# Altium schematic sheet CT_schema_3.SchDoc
size 349 x 342 mm
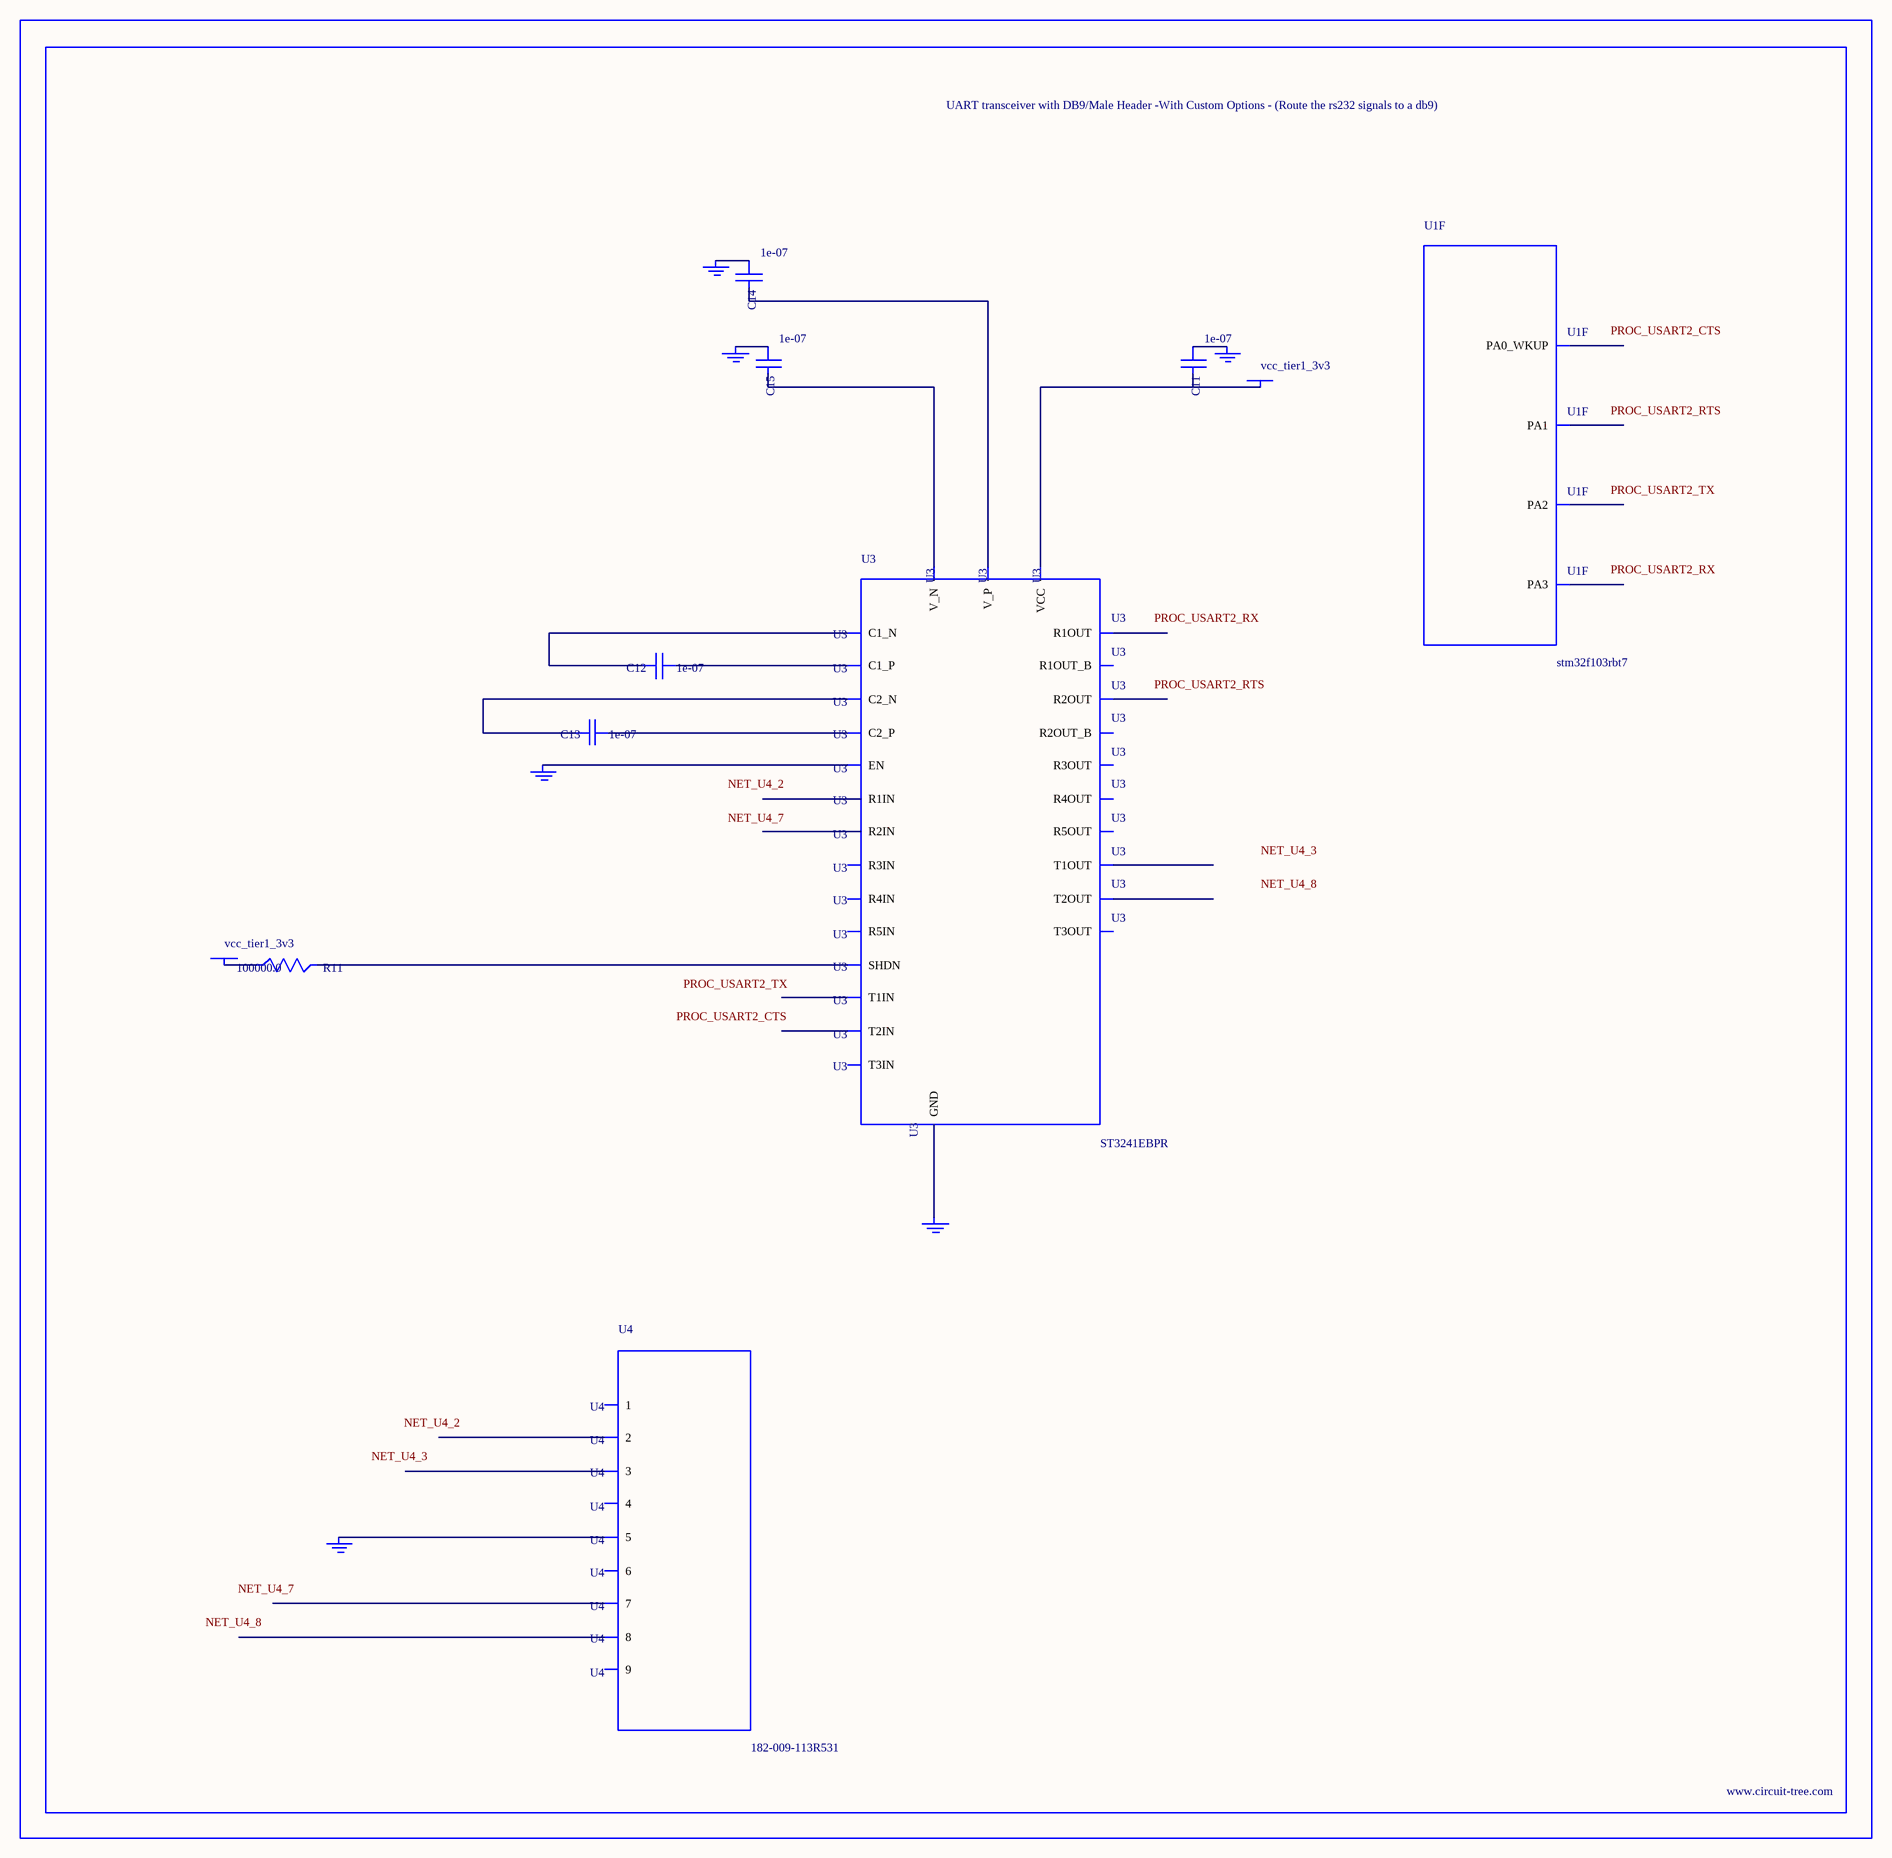
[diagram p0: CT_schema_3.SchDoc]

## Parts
BORDER2  (no value)
C11  1e-07  [C0402]
C12  1e-07  [C0402]
C13  1e-07  [C0402]
C14  1e-07  [C0402]
C15  1e-07  [C0402]
GND_INSTANCE_2_0  (no value)
GND_INSTANCE_2_1  (no value)
GND_INSTANCE_2_2  (no value)
GND_INSTANCE_2_3  (no value)
GND_INSTANCE_2_4  (no value)
GND_INSTANCE_2_5  (no value)
POWER_INSTANCE_2_0  vcc_tier1_3v3
POWER_INSTANCE_2_1  vcc_tier1_3v3
R11  100000.0  [R0603]
U1  stm32f103rbt7  [LQFP64]  (part F of 7)
U3  ST3241EBPR  [SSOP-28]
U4  182-009-113R531  [182-009-MALE]

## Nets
NetC11_1: C11.1 GND_INSTANCE_2_2.0(GND)
NetC11_2: C11.2 POWER_INSTANCE_2_1.0(PWR) U3.26(VCC)
NetC12_1: C12.1 U3.28(C1_P)
NetC12_2: C12.2 U3.24(C1_N)
NetC13_1: C13.1 U3.1(C2_P)
NetC13_2: C13.2 U3.2(C2_N)
NetC14_1: C14.1 GND_INSTANCE_2_3.0(GND)
NetC14_2: C14.2 U3.27(V_P)
NetC15_1: C15.1 GND_INSTANCE_2_0.0(GND)
NetC15_2: C15.2 U3.3(V_N)
NetGND_INSTANCE_2_1_0: GND_INSTANCE_2_1.0(GND) U3.23(EN)
NetGND_INSTANCE_2_4_0: GND_INSTANCE_2_4.0(GND) U3.25(GND)
NetGND_INSTANCE_2_5_0: GND_INSTANCE_2_5.0(GND) U4.5
NetPOWER_INSTANCE_2_0_0: POWER_INSTANCE_2_0.0(PWR) R11.1
NetR11_2: R11.2 U3.22(SHDN)

Not connected (* = marked no-connect by the designer): U1 14(PA0_WKUP) 15(PA1) 16(PA2) 17(PA3); U3 4(R1IN) 5(R2IN) 6(R3IN) 7(R4IN) 8(R5IN) 9(T1OUT) 10(T2OUT) 11(T3OUT) 12(T3IN) 13(T2IN) 14(T1IN) 15(R5OUT) 16(R4OUT) 17(R3OUT) 18(R2OUT) 19(R1OUT) 20(R2OUT_B) 21(R1OUT_B); U4 1 2 3 4 6 7 8 9

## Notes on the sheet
- Labels drawn without touching a wire or pin: NET_U4_2, NET_U4_3, NET_U4_7, NET_U4_8, PROC_USART2_CTS, PROC_USART2_RTS, PROC_USART2_RX, PROC_USART2_TX

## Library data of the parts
BORDER2 = BORDER_PAGE2
C11-C15 = C0402C104K3RACTU
GND_INSTANCE_2_0-GND_INSTANCE_2_5 = GND
POWER_INSTANCE_2_0 POWER_INSTANCE_2_1 = PWR
R11 = RC0603JR-07100KL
